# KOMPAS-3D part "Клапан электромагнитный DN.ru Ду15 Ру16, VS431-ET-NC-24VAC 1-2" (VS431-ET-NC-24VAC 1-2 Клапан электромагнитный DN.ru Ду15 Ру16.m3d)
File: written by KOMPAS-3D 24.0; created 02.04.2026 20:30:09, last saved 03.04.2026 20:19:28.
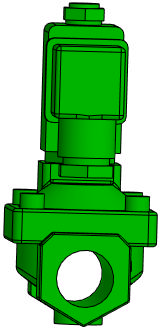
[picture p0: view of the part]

Document properties: Автор: artio; Полное имя файла: C:\Users\artio\OneDrive\Рабочий стол\Клапан электромагнитный DN.ru\VS431\VS431-ET-NC\VS431-ET-NC-24VAC\Ду15\VS431-ET-NC-24VAC 1-2 Клапан электромагнитный DN.ru Ду15 Ру16.m3d

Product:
- Body: Тело 1  | qty 1
    Масса: 1.030062
- Part/product: Клапан электромагнитный DN.ru Ду15 Ру16  | designation VS431-ET-NC-24VAC 1-2
    Масса: 0.732
    Раздел спецификации: Прочие изделия
    Примечание: D130-05635
    additional columns: ef56311e-7521-43dc-8291-0e6108b3d81d; VS400-ET-NC-220VAC 1-2; artio; c; Шероховатость не задана; Да

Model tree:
1. Операция без истории:1

Expressions: VS431-ET-NC-24VAC 1-2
